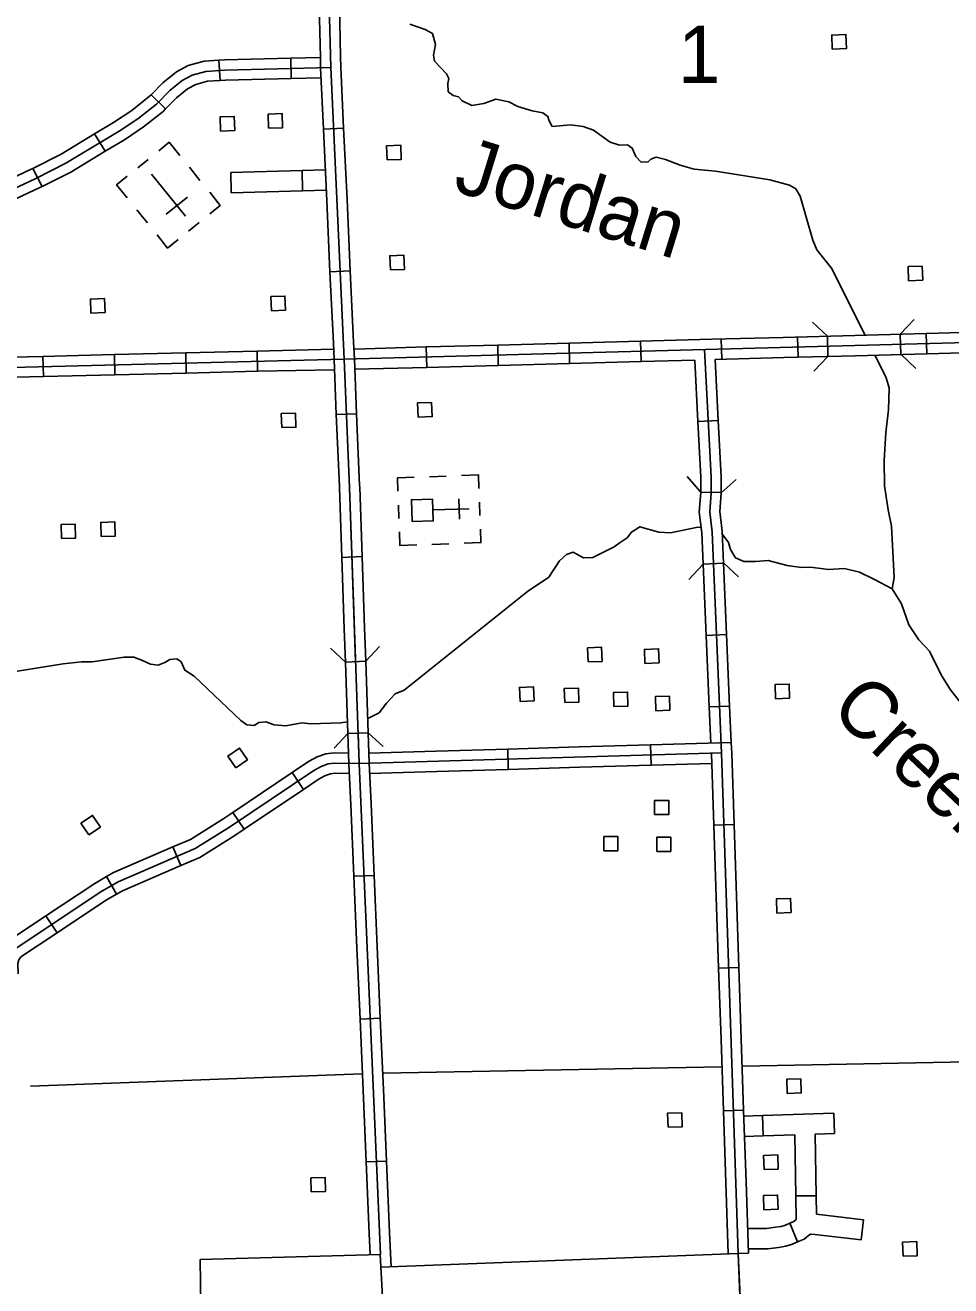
# Model space of a CAD drawing. Extents: x -0.3 to 2.65, y 0 to 1.9.
# Drawn here: x 0.4128 to 0.4946, y 0.3259 to 0.4374 of the extents above; entities that cross this region are included whole.
import ezdxf

# ---------------------------------------------------------------- set-up
doc = ezdxf.new("R2010")
doc.units = 0
for name, color, linetype in [('Level 14', 7, 'Continuous'), ('Level 15', 7, 'Continuous'), ('Level 18', 7, 'Continuous'), ('Level 19', 7, 'Continuous'), ('Level 20', 7, 'Continuous'), ('Level 29', 7, 'Continuous'), ('Level 32', 7, 'Continuous'), ('Level 35', 7, 'Continuous'), ('Level 6', 7, 'Continuous')]:
    doc.layers.add(name, color=color, linetype=linetype)

msp = doc.modelspace()

# ---------------------------------------------------------------- linework, layer by layer
at = {"layer": 'Level 14'}
for points in [[(0.44678, 0.43747), (0.44814, 0.437), (0.44878, 0.43664), (0.44904, 0.43569), (0.44888, 0.43473), (0.44897, 0.43421), (0.45004, 0.4331), (0.45023, 0.43268), (0.45015, 0.43222), (0.45016, 0.4315), (0.45061, 0.43117), (0.45108, 0.43106), (0.45141, 0.4307), (0.45226, 0.4303), (0.45333, 0.43046), (0.45438, 0.43085), (0.45555, 0.43061), (0.45635, 0.4302), (0.4576, 0.42983), (0.45856, 0.42964), (0.459, 0.42932), (0.45912, 0.42894), (0.45938, 0.42842), (0.46099, 0.42858), (0.46211, 0.42842), (0.46303, 0.42812), (0.46449, 0.42705), (0.46534, 0.42679), (0.46604, 0.42681), (0.46645, 0.42652), (0.46678, 0.42578), (0.46725, 0.42528), (0.46787, 0.42531), (0.46811, 0.42554), (0.46858, 0.42572), (0.46941, 0.42553), (0.47069, 0.42502), (0.47192, 0.42465), (0.47382, 0.42448), (0.47864, 0.42373), (0.48037, 0.42325), (0.48092, 0.42292), (0.48131, 0.42228), (0.48243, 0.41838), (0.48278, 0.41753), (0.48407, 0.41592), (0.48705, 0.40998)], [(0.48792, 0.40823), (0.48889, 0.4063), (0.48917, 0.40534), (0.48913, 0.40339), (0.48888, 0.40138), (0.48873, 0.39891), (0.48877, 0.39667), (0.48908, 0.39455), (0.4894, 0.3931), (0.48962, 0.38857), (0.48945, 0.38755)], [(0.46486, 0.39126), (0.4653, 0.39161), (0.46601, 0.39206), (0.46639, 0.39258), (0.46714, 0.39305), (0.46881, 0.39258), (0.46984, 0.39252), (0.47226, 0.39301), (0.47254, 0.39298)], [(0.47439, 0.39246), (0.47496, 0.39166), (0.47515, 0.39104), (0.47558, 0.39031), (0.47634, 0.38999), (0.47737, 0.38999), (0.47849, 0.39007), (0.48017, 0.38963), (0.48142, 0.38946), (0.48223, 0.38947), (0.48382, 0.38928), (0.48522, 0.38936), (0.48656, 0.38902), (0.48789, 0.3884), (0.48945, 0.38755), (0.49028, 0.38622), (0.49091, 0.38439), (0.49182, 0.38306), (0.49275, 0.38204), (0.49382, 0.37991), (0.49462, 0.37863), (0.49549, 0.37752)], [(0.44306, 0.37611), (0.44406, 0.37661), (0.44472, 0.37745), (0.4455, 0.37828), (0.44627, 0.37861), (0.4572, 0.38732), (0.45909, 0.3886), (0.46003, 0.39005), (0.46064, 0.3906), (0.46122, 0.39079), (0.46215, 0.3903), (0.46298, 0.39032), (0.46486, 0.39126)], [(0.40965, 0.3799), (0.41613, 0.38094), (0.41774, 0.38111), (0.41869, 0.3811), (0.42151, 0.38153), (0.42237, 0.38151), (0.42314, 0.38123), (0.42385, 0.38089), (0.42452, 0.38082), (0.42511, 0.38105), (0.42554, 0.3813), (0.42617, 0.38137), (0.42655, 0.38112), (0.42689, 0.38036), (0.42771, 0.37983), (0.43183, 0.37592), (0.43236, 0.37554), (0.433, 0.37547), (0.43344, 0.37575), (0.43405, 0.3758), (0.43479, 0.37553), (0.4358, 0.37545), (0.43727, 0.37572), (0.43801, 0.37562), (0.44067, 0.37572), (0.44124, 0.3758)]]:
    msp.add_lwpolyline(points, dxfattribs=at)
at = {"layer": 'Level 15'}
for p, q in [((0.43002, 0.43251), (0.42989, 0.4343)), ((0.43629, 0.43268), (0.43625, 0.43447)), ((0.42517, 0.42998), (0.4239, 0.43124)), ((0.41983, 0.42624), (0.4189, 0.42778)), ((0.41426, 0.42313), (0.41345, 0.42473)), ((0.43099, 0.42256), (0.43094, 0.42436)), ((0.4373, 0.42274), (0.43725, 0.42454)), ((0.49246, 0.41013), (0.4925, 0.40834)), ((0.44098, 0.40786), (0.49976, 0.40945)), ((0.45456, 0.40911), (0.45461, 0.40731)), ((0.46088, 0.40928), (0.46092, 0.40748)), ((0.46719, 0.40945), (0.46724, 0.40765)), ((0.47433, 0.40964), (0.47438, 0.40785)), ((0.48107, 0.40983), (0.48112, 0.40803)), ((0.48372, 0.4099), (0.48377, 0.4081)), ((0.49016, 0.41007), (0.49021, 0.40828)), ((0.41438, 0.40632), (0.41433, 0.40811)), ((0.42069, 0.40647), (0.42065, 0.40827)), ((0.42701, 0.40663), (0.42696, 0.40842)), ((0.43332, 0.40679), (0.43328, 0.40858)), ((0.44824, 0.40894), (0.44829, 0.40714)), ((0.47406, 0.40245), (0.47227, 0.40235)), ((0.47431, 0.39608), (0.47252, 0.3961)), ((0.47453, 0.38983), (0.47273, 0.38975)), ((0.4748, 0.38352), (0.473, 0.38344)), ((0.47506, 0.3772), (0.47327, 0.37713)), ((0.47436, 0.37306), (0.4423, 0.37211)), ((0.43738, 0.36983), (0.43637, 0.37132)), ((0.43213, 0.36631), (0.43113, 0.3678)), ((0.42653, 0.36309), (0.42581, 0.36474)), ((0.42085, 0.36056), (0.41995, 0.36212)), ((0.4156, 0.35716), (0.4146, 0.35865)), ((0.48428, 0.3412), (0.48434, 0.33941)), ((0.47797, 0.34099), (0.47803, 0.33919)), ((0.48093, 0.33389), (0.48273, 0.33391)), ((0.48039, 0.33148), (0.48108, 0.32982)), ((0.48691, 0.33178), (0.4867, 0.33))]:
    msp.add_line(p, q, dxfattribs=at)
for points in [[(0.43629, 0.54164), (0.43657, 0.53337), (0.43633, 0.53124), (0.43633, 0.53067), (0.4366, 0.52918), (0.43662, 0.52767), (0.43876, 0.47172), (0.43871, 0.4713), (0.43828, 0.47018), (0.43812, 0.4696), (0.43808, 0.46862), (0.43966, 0.43912), (0.43979, 0.43364), (0.44098, 0.40786)], [(0.38476, 0.41504), (0.38694, 0.41592), (0.38772, 0.41614), (0.38854, 0.41624), (0.38956, 0.41651), (0.39245, 0.41778), (0.39906, 0.41995), (0.40257, 0.42085), (0.40461, 0.42105), (0.40873, 0.4218), (0.41063, 0.42239), (0.41369, 0.42383), (0.41637, 0.42519), (0.42106, 0.42801), (0.42272, 0.42911), (0.42437, 0.43042), (0.42555, 0.43162), (0.42664, 0.43251), (0.42753, 0.43297), (0.42875, 0.4333), (0.43043, 0.43342), (0.43979, 0.43364)], [(0.4239, 0.43124), (0.42494, 0.43229), (0.42613, 0.43327), (0.42719, 0.43383), (0.4286, 0.43421), (0.42989, 0.4343)], [(0.42989, 0.4343), (0.43039, 0.43434), (0.43625, 0.43447)], [(0.43625, 0.43447), (0.43885, 0.43453)], [(0.42517, 0.42998), (0.42615, 0.43096), (0.42712, 0.43177), (0.42785, 0.43215), (0.4289, 0.43243), (0.43002, 0.43251)], [(0.43002, 0.43251), (0.43048, 0.43254), (0.43629, 0.43268)], [(0.43629, 0.43268), (0.43891, 0.43274)], [(0.4189, 0.42778), (0.42057, 0.42878), (0.42218, 0.42985), (0.42376, 0.4311), (0.4239, 0.43124)], [(0.41983, 0.42624), (0.42153, 0.42726), (0.42324, 0.4284), (0.42496, 0.42976), (0.42517, 0.42998)], [(0.41345, 0.42473), (0.41593, 0.42599), (0.4189, 0.42778)], [(0.41426, 0.42313), (0.4168, 0.42441), (0.41983, 0.42624)], [(0.40967, 0.42305), (0.41029, 0.42324), (0.41329, 0.42465), (0.41345, 0.42473)], [(0.43725, 0.42454), (0.43929, 0.42459)], [(0.43094, 0.42436), (0.43725, 0.42454)], [(0.40998, 0.42126), (0.41094, 0.42156), (0.41407, 0.42304), (0.41426, 0.42313)], [(0.43099, 0.42256), (0.4373, 0.42274)], [(0.4373, 0.42274), (0.43937, 0.4228)], [(0.40873, 0.4218), (0.40902, 0.42147), (0.40922, 0.42026), (0.40958, 0.40874), (0.40972, 0.408), (0.4099, 0.40761), (0.41012, 0.40739), (0.41055, 0.40722), (0.41157, 0.40713), (0.44098, 0.40786)], [(0.48614, 0.40996), (0.49246, 0.41013)], [(0.49246, 0.41013), (0.49877, 0.41031)], [(0.41048, 0.40932), (0.4105, 0.40884), (0.4106, 0.40828), (0.41065, 0.40817), (0.41076, 0.40812), (0.4116, 0.40804), (0.41433, 0.40811)], [(0.44824, 0.40894), (0.45456, 0.40911)], [(0.45456, 0.40911), (0.46088, 0.40928)], [(0.46088, 0.40928), (0.46719, 0.40945)], [(0.46719, 0.40945), (0.47351, 0.40962)], [(0.47351, 0.40962), (0.47982, 0.40979)], [(0.47982, 0.40979), (0.48614, 0.40996)], [(0.41433, 0.40811), (0.42065, 0.40827)], [(0.42065, 0.40827), (0.42696, 0.40842)], [(0.42696, 0.40842), (0.43328, 0.40858)], [(0.43328, 0.40858), (0.44002, 0.40875)], [(0.44193, 0.40876), (0.44824, 0.40894)], [(0.47285, 0.40871), (0.47344, 0.39744), (0.47343, 0.39605), (0.47331, 0.39437), (0.47353, 0.39258), (0.47436, 0.37306), (0.47584, 0.3288)], [(0.47378, 0.40783), (0.47987, 0.408)], [(0.47987, 0.408), (0.48619, 0.40817)], [(0.48619, 0.40817), (0.4925, 0.40834)], [(0.4925, 0.40834), (0.49882, 0.40851)], [(0.42701, 0.40663), (0.43332, 0.40679)], [(0.43332, 0.40679), (0.4401, 0.40693)], [(0.4419, 0.40697), (0.44829, 0.40714)], [(0.44829, 0.40714), (0.45461, 0.40731)], [(0.45461, 0.40731), (0.46092, 0.40748)], [(0.46092, 0.40748), (0.46724, 0.40765)], [(0.46724, 0.40765), (0.47199, 0.40778)], [(0.47199, 0.40778), (0.47227, 0.40235)], [(0.47378, 0.40783), (0.47406, 0.40245)], [(0.41066, 0.40623), (0.41438, 0.40632)], [(0.41438, 0.40632), (0.42069, 0.40647)], [(0.42069, 0.40647), (0.42701, 0.40663)], [(0.47227, 0.40235), (0.47253, 0.39742), (0.47252, 0.3961)], [(0.47406, 0.40245), (0.47432, 0.39746), (0.47431, 0.39608)], [(0.47252, 0.3961), (0.47252, 0.39608), (0.47239, 0.39435), (0.47262, 0.3925), (0.47273, 0.38975)], [(0.47431, 0.39608), (0.47431, 0.39601), (0.4742, 0.39439), (0.47441, 0.39265), (0.47453, 0.38983)], [(0.47273, 0.38975), (0.473, 0.38344)], [(0.47453, 0.38983), (0.4748, 0.38352)], [(0.473, 0.38344), (0.47327, 0.37713)], [(0.4748, 0.38352), (0.47506, 0.3772)], [(0.47327, 0.37713), (0.47341, 0.37392)], [(0.47506, 0.3772), (0.4752, 0.37398)], [(0.44137, 0.37304), (0.44008, 0.37307), (0.43934, 0.37298), (0.43858, 0.3727), (0.43782, 0.3723), (0.43637, 0.37132)], [(0.4423, 0.37211), (0.44013, 0.37215), (0.43955, 0.37209), (0.43895, 0.37186), (0.43829, 0.37151), (0.43082, 0.36649), (0.42781, 0.3646), (0.42098, 0.36166), (0.4194, 0.36075), (0.41176, 0.35566), (0.41139, 0.35514), (0.41123, 0.35455), (0.41148, 0.34415), (0.4114, 0.34371), (0.41124, 0.34346), (0.41097, 0.34329), (0.41016, 0.34319), (0.38476, 0.34251)], [(0.43637, 0.37132), (0.43113, 0.3678)], [(0.44143, 0.37125), (0.44017, 0.37127), (0.43976, 0.37122), (0.43931, 0.37105), (0.43875, 0.37076), (0.43738, 0.36983)], [(0.43738, 0.36983), (0.43213, 0.36631)], [(0.43113, 0.3678), (0.43032, 0.36726), (0.42738, 0.36541), (0.42581, 0.36474)], [(0.43213, 0.36631), (0.4313, 0.36575), (0.42822, 0.36382), (0.42653, 0.36309)], [(0.42581, 0.36474), (0.42057, 0.36247), (0.41995, 0.36212)], [(0.42653, 0.36309), (0.42138, 0.36087), (0.42085, 0.36056)], [(0.41995, 0.36212), (0.41892, 0.36152), (0.4146, 0.35865)], [(0.42085, 0.36056), (0.41986, 0.36), (0.4156, 0.35716)], [(0.4146, 0.35865), (0.41111, 0.35632), (0.41055, 0.35553), (0.41032, 0.35465), (0.41035, 0.35348)], [(0.4156, 0.35716), (0.41238, 0.35502), (0.4122, 0.35476), (0.41212, 0.35444), (0.41214, 0.35352)], [(0.48428, 0.3412), (0.47797, 0.34099)], [(0.47797, 0.34099), (0.47631, 0.34093)], [(0.47803, 0.33919), (0.47637, 0.33914)], [(0.48085, 0.33929), (0.47803, 0.33919)], [(0.48085, 0.33929), (0.48093, 0.33389)], [(0.48434, 0.33941), (0.48265, 0.33935)], [(0.48265, 0.33935), (0.48273, 0.33391)], [(0.48093, 0.33389), (0.48096, 0.3318)], [(0.48273, 0.33391), (0.48275, 0.33228)], [(0.48691, 0.33178), (0.48275, 0.33228)], [(0.48039, 0.33148), (0.48002, 0.33132), (0.47963, 0.3312), (0.47912, 0.33112), (0.47832, 0.33101), (0.47666, 0.33102)], [(0.48096, 0.3318), (0.48074, 0.33162), (0.48039, 0.33148)], [(0.4867, 0.33), (0.4826, 0.33049), (0.48225, 0.3305), (0.48222, 0.3305), (0.48217, 0.33047), (0.48166, 0.33006), (0.48108, 0.32982)], [(0.47584, 0.3288), (0.47646, 0.31348), (0.47666, 0.30639), (0.477, 0.29808)], [(0.48108, 0.32982), (0.48064, 0.32964), (0.48004, 0.32945), (0.47939, 0.32934), (0.47844, 0.32921), (0.47672, 0.32922)]]:
    msp.add_lwpolyline(points, dxfattribs=at)
for points in [[(0.46844, 0.36761), (0.46844, 0.36885), (0.46969, 0.36885), (0.46969, 0.36761)], [(0.46395, 0.36441), (0.46395, 0.36566), (0.46519, 0.36566), (0.46519, 0.36441)]]:
    msp.add_lwpolyline(points, close=True, dxfattribs=at)
at = {"layer": 'Level 18'}
for p, q in [((0.43914, 0.42821), (0.44093, 0.42829)), ((0.44152, 0.41567), (0.43972, 0.41558)), ((0.44028, 0.40296), (0.44208, 0.40304)), ((0.44256, 0.39041), (0.44077, 0.39034)), ((0.44077, 0.39034), (0.44077, 0.39034)), ((0.44109, 0.38109), (0.44288, 0.38116)), ((0.44311, 0.37484), (0.44131, 0.37478)), ((0.45544, 0.3734), (0.45549, 0.3716)), ((0.46812, 0.37197), (0.46807, 0.37377)), ((0.47547, 0.36672), (0.47367, 0.36666)), ((0.44183, 0.36215), (0.44362, 0.36222)), ((0.4741, 0.35403), (0.47589, 0.35409)), ((0.44417, 0.3496), (0.44238, 0.34952)), ((0.44238, 0.34952), (0.44238, 0.34952)), ((0.47631, 0.34146), (0.47452, 0.3414)), ((0.44293, 0.3369), (0.44472, 0.33697)), ((0.47494, 0.32877), (0.47674, 0.32883))]:
    msp.add_line(p, q, dxfattribs=at)
for points in [[(0.43657, 0.53337), (0.43633, 0.53124), (0.43633, 0.53067), (0.4366, 0.52918), (0.43662, 0.52767), (0.43876, 0.47172), (0.43871, 0.4713), (0.43828, 0.47018), (0.43812, 0.4696), (0.43808, 0.46862), (0.43966, 0.43912), (0.43979, 0.43364), (0.44098, 0.40786)], [(0.43867, 0.44083), (0.43876, 0.43909), (0.43887, 0.43454)], [(0.43956, 0.44087), (0.43966, 0.43912), (0.43979, 0.43364), (0.44098, 0.40786)], [(0.44066, 0.43458), (0.44055, 0.43916), (0.44046, 0.44092)], [(0.43887, 0.43454), (0.43889, 0.43361), (0.43914, 0.42821)], [(0.44093, 0.42829), (0.44069, 0.43367), (0.44066, 0.43458)], [(0.43914, 0.42821), (0.43943, 0.4219)], [(0.44093, 0.42829), (0.44123, 0.42198)], [(0.43943, 0.4219), (0.43972, 0.41558)], [(0.44123, 0.42198), (0.44152, 0.41567)], [(0.43972, 0.41558), (0.44002, 0.40927)], [(0.44181, 0.40936), (0.44152, 0.41567)], [(0.44002, 0.40927), (0.44008, 0.40782), (0.44028, 0.40296)], [(0.44208, 0.40304), (0.44188, 0.4079), (0.44181, 0.40936)], [(0.44098, 0.40786), (0.44145, 0.39651), (0.4423, 0.37211), (0.44418, 0.32872)], [(0.44098, 0.40786), (0.44145, 0.39651), (0.44198, 0.38112)], [(0.44028, 0.40296), (0.44055, 0.39665)], [(0.44208, 0.40304), (0.44234, 0.39673)], [(0.44234, 0.39673), (0.44235, 0.39655), (0.44256, 0.39041)], [(0.44055, 0.39665), (0.44055, 0.39648), (0.44077, 0.39034)], [(0.44077, 0.39034), (0.44098, 0.38403)], [(0.44278, 0.38409), (0.44256, 0.39041)], [(0.44098, 0.38403), (0.44109, 0.38109)], [(0.44288, 0.38116), (0.44278, 0.38409)], [(0.44288, 0.38116), (0.44311, 0.37484)], [(0.44109, 0.38109), (0.44131, 0.37478)], [(0.44131, 0.37478), (0.4414, 0.37208), (0.44156, 0.36846)], [(0.4422, 0.37481), (0.4423, 0.37211), (0.44418, 0.32872)], [(0.44335, 0.36854), (0.44319, 0.37215), (0.44311, 0.37484)], [(0.45544, 0.3734), (0.44912, 0.37321)], [(0.46175, 0.37358), (0.45544, 0.3734)], [(0.46807, 0.37377), (0.46175, 0.37358)], [(0.47526, 0.37303), (0.47522, 0.37398), (0.46807, 0.37377)], [(0.47436, 0.37306), (0.4423, 0.37211)], [(0.44912, 0.37321), (0.44316, 0.37304)], [(0.47367, 0.36666), (0.47346, 0.37297)], [(0.47584, 0.3288), (0.47436, 0.37306)], [(0.47547, 0.36672), (0.47526, 0.37303)], [(0.44918, 0.37142), (0.44323, 0.37124)], [(0.45549, 0.3716), (0.44918, 0.37142)], [(0.45549, 0.3716), (0.46181, 0.37179)], [(0.46181, 0.37179), (0.46812, 0.37197)], [(0.47349, 0.37213), (0.46812, 0.37197)], [(0.44156, 0.36846), (0.44183, 0.36215)], [(0.44362, 0.36222), (0.44335, 0.36854)], [(0.47367, 0.36666), (0.47389, 0.36034)], [(0.47568, 0.3604), (0.47547, 0.36672)], [(0.44362, 0.36222), (0.4439, 0.35591)], [(0.44183, 0.36215), (0.4421, 0.35583)], [(0.47389, 0.36034), (0.4741, 0.35403)], [(0.47589, 0.35409), (0.47568, 0.3604)], [(0.4421, 0.35583), (0.44238, 0.34952)], [(0.4439, 0.35591), (0.44417, 0.3496)], [(0.47431, 0.34771), (0.4741, 0.35403)], [(0.4761, 0.34777), (0.47589, 0.35409)], [(0.44238, 0.34952), (0.44265, 0.34321)], [(0.44445, 0.34329), (0.44417, 0.3496)], [(0.47452, 0.3414), (0.47431, 0.34771)], [(0.47631, 0.34146), (0.4761, 0.34777)], [(0.44472, 0.33697), (0.44445, 0.34329)], [(0.44265, 0.34321), (0.44293, 0.3369)], [(0.47452, 0.3414), (0.47473, 0.33508)], [(0.47653, 0.33514), (0.47631, 0.34146)], [(0.44293, 0.3369), (0.4432, 0.33058)], [(0.44472, 0.33697), (0.44499, 0.33066)], [(0.47473, 0.33508), (0.47494, 0.32877)], [(0.47674, 0.32883), (0.47653, 0.33514)], [(0.4432, 0.33058), (0.44328, 0.3287)], [(0.44499, 0.33066), (0.44513, 0.32763)]]:
    msp.add_lwpolyline(points, dxfattribs=at)
at = {"layer": 'Level 19'}
for points in [[(0.48415, 0.43528), (0.48411, 0.43652), (0.48536, 0.43657), (0.4854, 0.43532)], [(0.43004, 0.42803), (0.43, 0.42928), (0.43125, 0.42932), (0.43129, 0.42808)], [(0.43428, 0.42828), (0.43424, 0.42952), (0.43549, 0.42957), (0.43553, 0.42832)], [(0.44478, 0.42548), (0.44473, 0.42673), (0.44598, 0.42677), (0.44602, 0.42553)], [(0.44506, 0.41576), (0.44501, 0.417), (0.44626, 0.41705), (0.44631, 0.4158)], [(0.4909, 0.4148), (0.49085, 0.41605), (0.4921, 0.41609), (0.49215, 0.41485)], [(0.43454, 0.41215), (0.4345, 0.4134), (0.43574, 0.41344), (0.43579, 0.4122)], [(0.41857, 0.41193), (0.41853, 0.41318), (0.41978, 0.41322), (0.41982, 0.41198)], [(0.44751, 0.40274), (0.44746, 0.40399), (0.44871, 0.40403), (0.44876, 0.40279)], [(0.43546, 0.40181), (0.43541, 0.40305), (0.43666, 0.4031), (0.43671, 0.40185)], [(0.41948, 0.39219), (0.41944, 0.39343), (0.42069, 0.39348), (0.42073, 0.39223)], [(0.41598, 0.392), (0.41593, 0.39324), (0.41718, 0.39329), (0.41722, 0.39204)], [(0.46255, 0.38111), (0.4625, 0.38235), (0.46375, 0.3824), (0.46379, 0.38115)], [(0.46758, 0.38097), (0.46753, 0.38221), (0.46878, 0.38226), (0.46883, 0.38101)], [(0.47913, 0.37785), (0.47909, 0.3791), (0.48034, 0.37914), (0.48038, 0.3779)], [(0.45653, 0.37761), (0.45648, 0.37885), (0.45773, 0.37889), (0.45777, 0.37765)], [(0.46049, 0.3775), (0.46044, 0.37875), (0.46169, 0.37879), (0.46174, 0.37755)], [(0.46483, 0.37715), (0.46479, 0.37839), (0.46604, 0.37844), (0.46608, 0.37719)], [(0.46854, 0.37679), (0.4685, 0.37804), (0.46974, 0.37808), (0.46979, 0.37684)], [(0.43139, 0.37174), (0.43069, 0.37277), (0.43172, 0.37348), (0.43242, 0.37245)], [(0.41839, 0.3658), (0.41769, 0.36683), (0.41872, 0.36753), (0.41942, 0.3665)], [(0.46862, 0.36435), (0.46862, 0.3656), (0.46987, 0.3656), (0.46987, 0.36435)], [(0.47925, 0.3589), (0.47921, 0.36015), (0.48046, 0.36019), (0.4805, 0.35895)], [(0.48016, 0.34295), (0.48012, 0.3442), (0.48136, 0.34424), (0.48141, 0.343)], [(0.46964, 0.33996), (0.46959, 0.34121), (0.47084, 0.34125), (0.47088, 0.34001)], [(0.47812, 0.33622), (0.47807, 0.33746), (0.47932, 0.33751), (0.47936, 0.33626)], [(0.43807, 0.33424), (0.43803, 0.33548), (0.43928, 0.33553), (0.43932, 0.33428)], [(0.47811, 0.33267), (0.47806, 0.33392), (0.47931, 0.33396), (0.47936, 0.33272)], [(0.49041, 0.32856), (0.49037, 0.3298), (0.49162, 0.32985), (0.49166, 0.3286)]]:
    msp.add_lwpolyline(points, close=True, dxfattribs=at)
at = {"layer": 'Level 20'}
for points in [[(0.47621, 0.34535), (0.50687, 0.34594)], [(0.41324, 0.34358), (0.44258, 0.34468)], [(0.44439, 0.34473), (0.47439, 0.34531)]]:
    msp.add_lwpolyline(points, dxfattribs=at)
at = {"layer": 'Level 29'}
for points in [[(0.49016, 0.41007), (0.4914, 0.41137)], [(0.48241, 0.41114), (0.48372, 0.4099)], [(0.48376, 0.40809), (0.48253, 0.40679)], [(0.49153, 0.40703), (0.49023, 0.40827)], [(0.47248, 0.39615), (0.47131, 0.3975)], [(0.47566, 0.39722), (0.47431, 0.39605)], [(0.47147, 0.38839), (0.47269, 0.38972)], [(0.47455, 0.38982), (0.47587, 0.38861)], [(0.44109, 0.38109), (0.43977, 0.38232)], [(0.4441, 0.38247), (0.44288, 0.38116)], [(0.44009, 0.37347), (0.44131, 0.37478)], [(0.44311, 0.37484), (0.44442, 0.37362)]]:
    msp.add_lwpolyline(points, dxfattribs=at)
at = {"layer": 'Level 32'}
for p, q in [((0.42364, 0.42553), (0.42271, 0.42478)), ((0.42822, 0.42367), (0.42728, 0.42483)), ((0.42694, 0.4205), (0.42393, 0.42423)), ((0.42543, 0.42237), (0.42543, 0.42237)), ((0.42543, 0.42237), (0.42543, 0.42237)), ((0.42712, 0.42219), (0.42524, 0.42068)), ((0.42311, 0.42049), (0.42263, 0.42108)), ((0.42311, 0.42049), (0.42357, 0.41991)), ((0.42722, 0.41919), (0.42815, 0.41994)), ((0.45001, 0.39753), (0.44851, 0.39747)), ((0.44577, 0.39497), (0.44581, 0.39378)), ((0.45204, 0.39464), (0.44882, 0.39453)), ((0.45111, 0.39551), (0.45117, 0.39371)), ((0.45299, 0.39403), (0.45295, 0.39523)), ((0.44949, 0.39152), (0.44873, 0.39149)), ((0.44949, 0.39152), (0.45022, 0.39155))]:
    msp.add_line(p, q, dxfattribs=at)
for points in [[(0.42457, 0.42629), (0.4255, 0.42704), (0.42644, 0.42587)], [(0.42179, 0.42212), (0.42085, 0.42328), (0.42178, 0.42403)], [(0.42908, 0.4207), (0.43002, 0.42145), (0.42908, 0.42262)], [(0.42629, 0.41844), (0.42536, 0.41769), (0.42442, 0.41886)], [(0.44718, 0.39742), (0.44568, 0.39737), (0.44573, 0.39618)], [(0.4529, 0.39643), (0.45286, 0.39763), (0.45136, 0.39757)], [(0.44586, 0.39259), (0.4459, 0.39139), (0.44739, 0.39145)], [(0.45303, 0.39284), (0.45307, 0.39165), (0.45158, 0.3916)]]:
    msp.add_lwpolyline(points, dxfattribs=at)
msp.add_lwpolyline([(0.44699, 0.3935), (0.44885, 0.39356), (0.44878, 0.3955), (0.44692, 0.39543)], close=True, dxfattribs=at)
at = {"layer": 'Level 35'}
for points in [[(0.47602, 0.32436), (0.47584, 0.3288)], [(0.44445, 0.32336), (0.44417, 0.32872)]]:
    msp.add_lwpolyline(points, dxfattribs=at)
at = {"layer": 'Level 6'}
for points in [[(0.4849, 0.29874), (0.48231, 0.29876), (0.47698, 0.29849), (0.47646, 0.31348), (0.4617, 0.31287), (0.46135, 0.3239), (0.47601, 0.32436), (0.47584, 0.3288), (0.44423, 0.3276), (0.44423, 0.32763)], [(0.44417, 0.32872), (0.42824, 0.32826), (0.42842, 0.31616), (0.41316, 0.31611), (0.41357, 0.2958), (0.42567, 0.29626)]]:
    msp.add_lwpolyline(points, dxfattribs=at)

# ---------------------------------------------------------------- texts
at = {"layer": 'Level 14'}
for s, rotation, p in [('Jordan', 342.8104, (0.45047, 0.4228)), ('Creek', 316.5911, (0.48381, 0.37676))]:
    msp.add_text(s, height=0.005055, rotation=rotation, dxfattribs=at).set_placement(p)
at = {"layer": 'Level 20'}
msp.add_text('1', height=0.00505, dxfattribs=at).set_placement((0.4705, 0.43229))

doc.saveas('drawing.dxf')
